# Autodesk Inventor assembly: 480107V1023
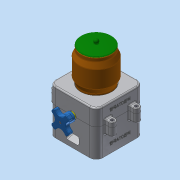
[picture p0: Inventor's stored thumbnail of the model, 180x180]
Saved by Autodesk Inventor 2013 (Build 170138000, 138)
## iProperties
Created: 2018-01
Part Number: 480107V1023
Document SubType Name: Assembly
Designer: dgall
Author: dgall
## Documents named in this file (9)
- C:\Users\dgall\Desktop\480107V1023.iam
- C:\Users\dgall\Desktop\480107V1023.ipt
- C:\Users\dgall\Desktop\본체커버.ipt
- C:\Users\dgall\Desktop\볼트 M3x12.ipt
- C:\Users\dgall\Desktop\볼트 M4x12.ipt
- C:\Users\dgall\Desktop\용기.ipt
- C:\Users\dgall\Desktop\용기캡.ipt
- C:\Users\dgall\Desktop\핸들.ipt
- C:\Users\dgall\Desktop\핸들축.ipt
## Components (3 placed, 3 different names)
1. 480107V1023:1
2. 핸들:1
3. 핸들축:1 — 각도:1
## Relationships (1: Angle 1)
- 각도:1 [Angle]: 핸들축:1
